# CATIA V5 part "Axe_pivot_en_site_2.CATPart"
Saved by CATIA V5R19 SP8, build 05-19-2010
Part number: Axe_pivot_en_site_2
Bounding box of the stored display mesh (mm): x 120 to 180, y 285.773 to 310.773, z 1389.16 to 1410.81
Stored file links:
  G:\EU_thinkMotion\CFAO_2010\MMS_groupe2\MMS_groupe2\OK\nrosalie\nrosalie_cfao_support_d_arme_legere_final\Axe_pivot_en_site_2.CATPart
  G:\EU_thinkMotion\CFAO_2010\MMS_groupe2\MMS_groupe2\OK\nrosalie\nrosalie_cfao_support_d_arme_legere_final\nrosalie_Support_d_arme_legere.CATProduct
  G:\EU_thinkMotion\CFAO_2010\MMS_groupe2\MMS_groupe2\OK\nrosalie\nrosalie_cfao_support_d_arme_legere_final\Squelette_piece_support.CATPart
  G:\EU_thinkMotion\CFAO_2010\MMS_groupe2\MMS_groupe2\OK\nrosalie\nrosalie_cfao_support_d_arme_legere_final\Piece_de_support.CATPart
  G:\EU_thinkMotion\CFAO_2010\MMS_groupe2\MMS_groupe2\OK\nrosalie\nrosalie_cfao_support_d_arme_legere_final\Bras.CATPart
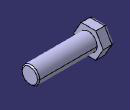
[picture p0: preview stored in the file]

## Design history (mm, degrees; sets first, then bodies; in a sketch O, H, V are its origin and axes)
Set1
  Sketch1 on Plane1, origin (150, 0, 0), H (0, 1, 0), V (0, 0, 1)
    circle A1 centre (298.2728, 1399.9851) radius 7.5
    reference projected circle E1 centre (298.2728, 1399.9851) radius 7.5 from edge of DatumCurve1
    coincidence: A1 E1
Set2
  Plane1: linked copy from another document
  DatumCurve1: linked copy from another document
  DatumSurface1: linked copy from another document
  DatumSurface2: linked copy from another document
  DatumCurve2: linked copy from another document
  Point1: linked copy from another document
Body1 (main body)
  Pad1: profile Sketch1, direction (1, 0, 0), up to face of DatumSurface1, offset 10, opposite side up to face of DatumSurface2
  Chamfer1: length 1, angle 45, on edge [end face of Pad1 | face of Pad1 from Sketch1.A1]
  Sketch2 on start face of Pad1, origin (130, 0, 0), H (0, -1, 0), V (0, 0, 1)
    construction circle A1 centre (-298.2728, 1399.9851) radius 12.5
    reference projected circle E1 centre (-298.2728, 1399.9851) radius 7.5 from edge of DatumCurve2
    reference projected circle E2 centre (-298.2728, 1399.9851) radius 7.5 from edge [face of Pad1 from Sketch1.A1 | start face of Pad1]
    line L1 (-304.5228, 1410.8104) -> (-292.0228, 1410.8104)
    point P2 (-304.5228, 1410.8104)
    point P3 (-292.0228, 1410.8104)
    line L2 (-292.0228, 1410.8104) -> (-285.7728, 1399.9851)
    point P4 (-292.0228, 1410.8104)
    point P5 (-285.7728, 1399.9851)
    line L3 (-285.7728, 1399.9851) -> (-292.0228, 1389.1598)
    point P6 (-292.0228, 1389.1598)
    line L4 (-292.0228, 1389.1598) -> (-304.5228, 1389.1598)
    point P7 (-304.5228, 1389.1598)
    line L5 (-304.5228, 1389.1598) -> (-310.7728, 1399.9851)
    point P8 (-310.7728, 1399.9851)
    line L6 (-304.5228, 1410.8104) -> (-310.7728, 1399.9851)
    point P9 (-310.7728, 1399.9851)
    construction line L7 (-256.5276, 1399.9851) -> (-337.3353, 1399.9851)
    reference projected point E3 (-298.2728, 1399.9851) from Point1
    axis line L8 (-298.2728, 1399.9851) -> (-282.2061, 1427.8135)
    distance A1 E2 = 5
    angle L7 L8 = 60
    concentricity: A1 E1
    coincidence: P2 A1, P3 A1, P4 L1, P4 A1, P5 A1, P6 A1, P7 A1, P8 A1, L6 P8, P9 A1, L7 E3, P8 L7, P5 L7, P3 L8, P3 P4, P8 P9
    horizontal: L1 H, L7 H
    symmetry: L1 L4 L7
  Pad2: profile Sketch2, direction (-1, 0, 0), length 10
  Fillet1: radius 2.5, on end face of Pad2
  SolidCombine1: FirstComponentProfile Sketch2, FirstComponentDirection Sketch2, SecondComponentProfile a sketch, SecondComponentDirection a sketch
